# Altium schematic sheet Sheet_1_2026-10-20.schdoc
size 129 x 49 mm
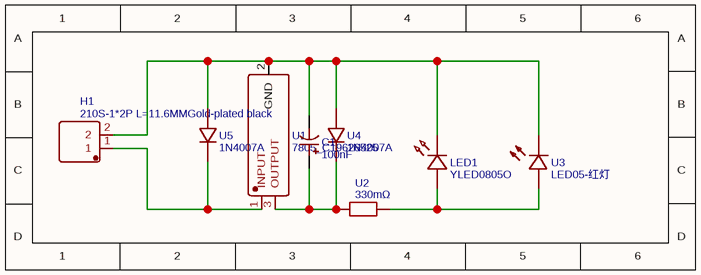
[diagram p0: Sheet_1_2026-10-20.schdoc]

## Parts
C1  100nF  [CAP-SMD_L2.2-W1.3-RD]
H1  210S-1*2P L=11.6MMGold-plated black  [HDR-TH_2P-P2.54-V-M-1]
LED1  YLED0805O  [LED0805-FD-GREEN]
U1  7805_C19626525  [TO-252-2_L6.6-W6.1-P4.57-LS9.9-BR-CW]
U2  330mΩ  [RES-TH_BD2.3-L6.5-P10.50-D0.5]
U3  LED05-红灯  [LED-TH_LED-3MM_RED]
U4  1N4007A  [DO-41_BD2.4-L4.7-P8.70-D0.9-RD]
U5  1N4007A  [DO-41_BD2.4-L4.7-P8.70-D0.9-RD]

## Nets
NetC1_1: C1.1 H1.2 LED1.2(C) U1.2(GND) U3.2 U4.2 U5.2
NetC1_2: C1.2 U1.3(OUTPUT) U2.1 U4.1
NetH1_1: H1.1 U1.1(INPUT) U5.1
NetLED1_1: LED1.1(A) U2.2 U3.1

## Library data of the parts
C1 = 100nF: Manufacturer: VISHAY(威世); Manufacturer Part: 195D104X0002C2T; nameAlias: Value; Contributor: lcsc
H1 = 210S-1*2P L=11.6MMGold-plated black: Manufacturer: Ckmtw(灿科盟); Manufacturer Part: B-2100S02P-A110; Contributor: LCSC
LED1 = YLED0805O: Manufacturer: YONGYUTAI(永裕泰); Contributor: lcsc
U1 = 7805_C19626525: Manufacturer: YFW(佑风微); Manufacturer Part: 7805; Contributor: lcsc
U2 = 330mΩ: Manufacturer: 华星机电; Manufacturer Part: CF1/4W-0.33Ω±5%T52; Contributor: lcsc; nameAlias: Value
U3 = LED05-红灯: Manufacturer: null; Contributor: LCSC
U4 U5 = 1N4007A: Manufacturer: LRC(乐山无线电); Contributor: lcsc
